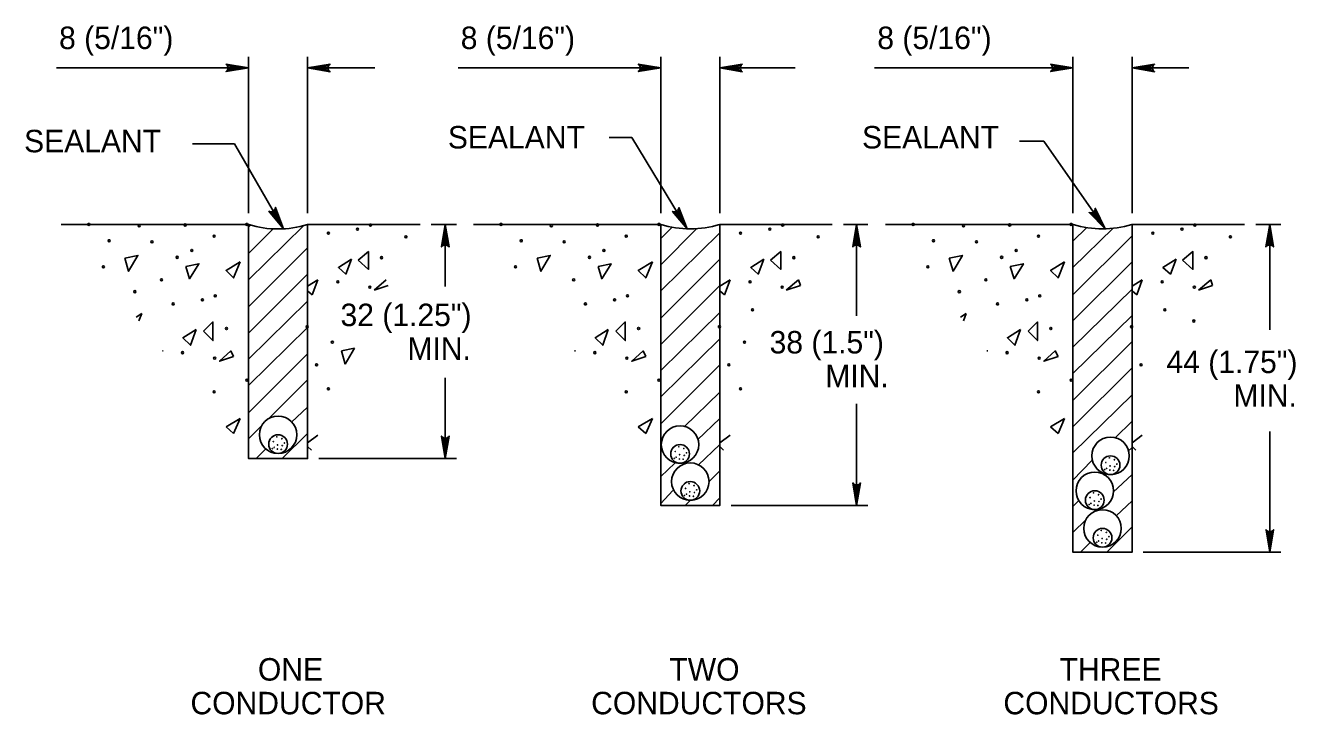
# Model space of a CAD drawing. Extents: x 2709 to 3899, y 22 to 1210.
# Drawn here: x 3729.8 to 3899.2, y 763.4 to 855.4 of the extents above; entities that cross this region are included whole.
import ezdxf

# ---------------------------------------------------------------- set-up
doc = ezdxf.new("R2010")
doc.units = 0
doc.layers.add('2', color=7, linetype='Continuous')
doc.layers.add('3', color=7, linetype='Continuous')

# ---------------------------------------------------------------- blocks, each defined once
blk = doc.blocks.new('RARROW')
at = {"layer": '3'}
blk.add_lwpolyline([(-2.2695, 0.285), (-2.184875, 0.12075), (0, 0), (-2.2695, 0.285), (-2.38575, 0.384625), (0, 0), (-2.183125, -0.108), (-2.262875, -0.2705), (0, 0), (-2.38575, -0.379125), (-2.262875, -0.2705)], dxfattribs=at)

msp = doc.modelspace()

# ---------------------------------------------------------------- linework, layer by layer
at = {"layer": '2'}
for p, q in [((3759.53, 830.32), (3759.53, 851.21)), ((3767.41, 830.32), (3767.41, 851.21)), ((3814.53, 830.32), (3814.53, 851.21)), ((3822.41, 830.32), (3822.41, 851.21)), ((3869.53, 830.32), (3869.53, 851.21)), ((3877.41, 830.32), (3877.41, 851.21)), ((3759.53, 849.71), (3733.89, 849.71)), ((3776.37, 849.71), (3767.41, 849.71)), ((3814.53, 849.71), (3787.48, 849.71)), ((3832.48, 849.71), (3822.41, 849.71)), ((3869.53, 849.71), (3843.06, 849.71)), ((3884.98, 849.71), (3877.41, 849.71)), ((3757.66, 839.57), (3752.03, 839.57)), ((3764.2, 828.24), (3757.66, 839.57)), ((3810.66, 840.44), (3807.66, 840.44)), ((3818.07, 828.25), (3810.66, 840.44)), ((3865.66, 839.94), (3862.41, 839.94)), ((3873.83, 828.25), (3865.66, 839.94)), ((3783.91, 828.82), (3787.28, 828.82)), ((3785.78, 828.82), (3785.78, 820.52)), ((3838.91, 828.82), (3842.16, 828.82)), ((3840.66, 828.82), (3840.66, 816.61)), ((3893.91, 828.82), (3897.28, 828.82)), ((3895.78, 828.82), (3895.78, 814.77)), ((3785.78, 808.33), (3785.78, 797.57)), ((3840.66, 804.88), (3840.66, 791.32)), ((3895.78, 801.2), (3895.78, 785.07)), ((3768.91, 797.57), (3787.28, 797.57)), ((3823.91, 791.32), (3842.16, 791.32)), ((3878.91, 785.07), (3897.28, 785.07))]:
    msp.add_line(p, q, dxfattribs=at)
for points in [[(3734.53, 828.82), (3759.53, 828.82), (3759.53, 797.57), (3767.41, 797.57), (3767.41, 828.82), (3782.41, 828.82)], [(3759.53, 828.44), (3759.81, 828.72)], [(3789.53, 828.82), (3814.53, 828.82), (3814.53, 791.32), (3822.41, 791.32), (3822.41, 828.82), (3837.41, 828.82)], [(3844.53, 828.82), (3869.53, 828.82), (3869.53, 785.07), (3877.41, 785.07), (3877.41, 828.82), (3892.41, 828.82)], [(3759.53, 821.44), (3766.87, 828.65)], [(3759.53, 824.94), (3762.83, 828.24)], [(3814.53, 826.94), (3816.05, 828.46)], [(3814.53, 823.44), (3819.36, 828.27)], [(3814.53, 819.94), (3822.41, 827.69)], [(3869.53, 826.57), (3871.37, 828.41)], [(3869.53, 823.07), (3874.91, 828.32)], [(3869.53, 819.44), (3877.41, 827.32)], [(3759.53, 817.82), (3767.41, 825.69)], [(3814.53, 816.32), (3822.41, 824.19)], [(3869.53, 815.94), (3877.41, 823.82)], [(3759.53, 814.32), (3767.41, 822.19)], [(3768.78, 821.44), (3767.41, 820.57)], [(3768.03, 819.44), (3768.78, 821.44)], [(3777.91, 821.44), (3776.28, 820.07)], [(3776.28, 820.07), (3778.16, 820.69)], [(3814.53, 812.82), (3822.41, 820.69)], [(3823.78, 821.44), (3822.41, 820.57)], [(3823.03, 819.44), (3823.78, 821.44)], [(3832.91, 821.44), (3831.28, 820.07)], [(3831.28, 820.07), (3833.16, 820.69)], [(3833.16, 820.69), (3832.91, 821.44)], [(3878.78, 821.44), (3877.41, 820.57)], [(3878.03, 819.44), (3878.78, 821.44)], [(3887.91, 821.44), (3886.28, 820.07)], [(3886.28, 820.07), (3888.16, 820.69)], [(3888.16, 820.69), (3887.91, 821.44)], [(3759.53, 810.82), (3767.41, 818.57)], [(3767.41, 819.94), (3768.03, 819.44)], [(3822.41, 819.94), (3823.03, 819.44)], [(3869.53, 812.44), (3877.41, 820.19)], [(3877.41, 819.94), (3878.03, 819.44)], [(3745.28, 816.94), (3744.53, 816.44)], [(3744.91, 815.94), (3745.28, 816.94)], [(3814.53, 809.32), (3822.41, 817.07)], [(3855.28, 816.94), (3854.53, 816.44)], [(3854.91, 815.94), (3855.28, 816.94)], [(3869.53, 808.94), (3877.41, 816.69)], [(3759.53, 807.32), (3767.41, 815.07)], [(3814.53, 805.82), (3822.41, 813.57)], [(3748.16, 811.94), (3748.03, 811.94)], [(3748.03, 811.94), (3748.16, 811.94)], [(3771.91, 811.94), (3773.66, 812.32)], [(3772.41, 810.19), (3771.91, 811.94)], [(3773.66, 812.32), (3772.41, 810.19)], [(3803.16, 811.94), (3803.03, 811.94)], [(3803.03, 811.94), (3803.16, 811.94)], [(3858.16, 811.94), (3858.03, 811.94)], [(3858.03, 811.94), (3858.16, 811.94)], [(3869.53, 805.32), (3877.41, 813.19)], [(3759.53, 803.69), (3767.41, 811.57)], [(3814.53, 802.19), (3822.41, 810.07)], [(3869.53, 801.82), (3877.41, 809.69)], [(3762.16, 802.82), (3767.41, 808.07)], [(3817.66, 801.82), (3822.41, 806.44)], [(3869.53, 798.32), (3877.41, 806.07)], [(3765.28, 802.44), (3767.41, 804.44)], [(3758.41, 802.94), (3756.53, 801.82)], [(3756.53, 801.82), (3757.53, 800.94)], [(3757.53, 800.94), (3758.41, 802.94)], [(3759.53, 800.19), (3761.28, 801.94)], [(3813.41, 802.94), (3811.53, 801.82)], [(3811.53, 801.82), (3812.53, 800.94)], [(3812.53, 800.94), (3813.41, 802.94)], [(3819.41, 800.07), (3822.41, 802.94)], [(3868.41, 802.94), (3866.53, 801.82)], [(3866.53, 801.82), (3867.53, 800.94)], [(3867.53, 800.94), (3868.41, 802.94)], [(3875.16, 800.32), (3877.41, 802.57)], [(3764.03, 797.57), (3767.41, 800.94)], [(3768.78, 800.69), (3767.41, 799.69)], [(3823.78, 800.69), (3822.41, 799.69)], [(3878.78, 800.69), (3877.41, 799.69)], [(3760.53, 797.57), (3761.78, 798.82)], [(3767.41, 799.19), (3767.91, 798.69)], [(3814.53, 798.69), (3814.66, 798.82)], [(3819.53, 796.69), (3822.41, 799.44)], [(3822.41, 799.19), (3822.91, 798.69)], [(3876.91, 798.57), (3877.41, 799.07)], [(3877.41, 799.19), (3877.91, 798.69)], [(3814.53, 795.19), (3816.41, 796.94)], [(3869.53, 794.69), (3872.03, 797.32)], [(3820.91, 794.44), (3822.41, 795.94)], [(3873.66, 795.32), (3873.78, 795.44)], [(3874.91, 793.07), (3877.41, 795.44)], [(3814.53, 791.57), (3816.16, 793.32)], [(3817.78, 791.32), (3818.41, 791.94)], [(3821.41, 791.32), (3822.41, 792.32)], [(3869.53, 791.19), (3870.28, 791.94)], [(3875.28, 789.94), (3877.41, 791.94)], [(3872.28, 790.44), (3872.53, 790.69)], [(3869.53, 787.69), (3871.28, 789.44)], [(3874.03, 785.07), (3877.41, 788.44)], [(3870.53, 785.07), (3871.78, 786.32)]]:
    msp.add_lwpolyline(points, dxfattribs=at)
for points in [[(3743.03, 824.32), (3744.78, 824.69), (3743.53, 822.57)], [(3758.41, 823.82), (3756.53, 822.69), (3757.53, 821.69)], [(3773.28, 824.19), (3771.53, 823.07), (3772.53, 822.19)], [(3774.16, 824.07), (3775.53, 825.19), (3775.53, 822.82)], [(3798.03, 824.32), (3799.78, 824.69), (3798.53, 822.57)], [(3813.41, 823.82), (3811.53, 822.69), (3812.53, 821.69)], [(3828.28, 824.19), (3826.53, 823.07), (3827.53, 822.19)], [(3829.16, 824.07), (3830.53, 825.19), (3830.53, 822.82)], [(3853.03, 824.32), (3854.78, 824.69), (3853.53, 822.57)], [(3868.41, 823.82), (3866.53, 822.69), (3867.53, 821.69)], [(3883.28, 824.19), (3881.53, 823.07), (3882.53, 822.19)], [(3884.16, 824.07), (3885.53, 825.19), (3885.53, 822.82)], [(3751.16, 823.19), (3752.91, 823.57), (3751.66, 821.57)], [(3806.16, 823.19), (3807.91, 823.57), (3806.66, 821.57)], [(3861.16, 823.19), (3862.91, 823.57), (3861.66, 821.57)], [(3753.53, 814.57), (3754.78, 815.82), (3754.78, 813.32)], [(3808.53, 814.57), (3809.78, 815.82), (3809.78, 813.32)], [(3863.53, 814.57), (3864.78, 815.82), (3864.78, 813.32)], [(3752.53, 814.82), (3750.78, 813.69), (3751.78, 812.69)], [(3807.53, 814.82), (3805.78, 813.69), (3806.78, 812.69)], [(3862.53, 814.82), (3860.78, 813.69), (3861.78, 812.69)], [(3757.53, 811.19), (3757.16, 811.94), (3755.66, 810.57)], [(3812.53, 811.19), (3812.16, 811.94), (3810.66, 810.57)], [(3867.53, 811.19), (3867.16, 811.94), (3865.66, 810.57)]]:
    msp.add_lwpolyline(points, close=True, dxfattribs=at)
for centre, radius in [((3738.21, 828.83), 0.138), ((3744.93, 828.63), 0.138), ((3751.08, 828.75), 0.138), ((3759.29, 828.83), 0.138), ((3775.79, 828.74), 0.138), ((3793.21, 828.83), 0.138), ((3799.93, 828.63), 0.138), ((3806.08, 828.75), 0.138), ((3814.29, 828.83), 0.138), ((3830.79, 828.74), 0.138), ((3848.21, 828.83), 0.138), ((3854.93, 828.63), 0.138), ((3861.08, 828.75), 0.138), ((3869.29, 828.83), 0.138), ((3885.79, 828.74), 0.138), ((3754.93, 827.26), 0.138), ((3770.18, 827.67), 0.138), ((3774.07, 828.2), 0.138), ((3780.53, 827.17), 0.138), ((3809.93, 827.26), 0.138), ((3825.18, 827.67), 0.138), ((3829.07, 828.2), 0.138), ((3835.53, 827.17), 0.138), ((3864.93, 827.26), 0.138), ((3880.18, 827.67), 0.138), ((3884.07, 828.2), 0.138), ((3890.53, 827.17), 0.138), ((3740.92, 826.65), 0.138), ((3746.65, 826.5), 0.138), ((3751.95, 825.35), 0.138), ((3795.92, 826.65), 0.138), ((3801.65, 826.5), 0.138), ((3806.95, 825.35), 0.138), ((3850.92, 826.65), 0.138), ((3856.65, 826.5), 0.138), ((3861.95, 825.35), 0.138), ((3750.01, 824.43), 0.138), ((3777.28, 824.39), 0.138), ((3805.01, 824.43), 0.138), ((3832.28, 824.39), 0.138), ((3860.01, 824.43), 0.138), ((3887.28, 824.39), 0.138), ((3740.16, 823.17), 0.138), ((3795.16, 823.17), 0.138), ((3850.16, 823.17), 0.138), ((3747.91, 821.42), 0.138), ((3771.44, 821.16), 0.138), ((3775.72, 820.44), 0.138), ((3802.91, 821.42), 0.138), ((3826.44, 821.16), 0.138), ((3830.72, 820.44), 0.138), ((3857.91, 821.42), 0.138), ((3881.44, 821.16), 0.138), ((3885.72, 820.44), 0.138), ((3744.36, 819.85), 0.138), ((3753.37, 818.75), 0.138), ((3755.09, 819.28), 0.138), ((3808.37, 818.75), 0.138), ((3810.09, 819.28), 0.138), ((3854.36, 819.85), 0.138), ((3863.37, 818.75), 0.138), ((3865.09, 819.28), 0.138), ((3749.47, 818.21), 0.138), ((3804.47, 818.21), 0.138), ((3826.78, 817.42), 0.138), ((3859.47, 818.21), 0.138), ((3881.78, 817.42), 0.138), ((3767.35, 815.17), 0.138), ((3822.35, 815.17), 0.138), ((3877.35, 815.17), 0.138), ((3885.64, 815.93), 0.138), ((3756.58, 814.93), 0.138), ((3811.58, 814.93), 0.138), ((3866.58, 814.93), 0.138), ((3750.73, 811.71), 0.138), ((3770.71, 813.11), 0.138), ((3805.73, 811.71), 0.138), ((3825.71, 813.11), 0.138), ((3860.73, 811.71), 0.138), ((3755.01, 810.98), 0.138), ((3768.61, 810.09), 0.138), ((3810.01, 810.98), 0.138), ((3823.61, 810.09), 0.138), ((3865.01, 810.98), 0.138), ((3878.61, 810.09), 0.138), ((3759.29, 808.04), 0.138), ((3770.18, 806.89), 0.138), ((3814.29, 808.04), 0.138), ((3825.18, 806.89), 0.138), ((3869.29, 808.04), 0.138), ((3754.93, 806.48), 0.138), ((3809.93, 806.48), 0.138), ((3864.93, 806.48), 0.138), ((3763.47, 800.75), 2.5), ((3817.1, 799.44), 2.5), ((3763.47, 799.5), 1.25), ((3762.72, 800.48), 0.0249), ((3763.31, 800.47), 0.0249), ((3763.98, 800.22), 0.0249), ((3874.54, 797.94), 2.5), ((3762.7, 798.91), 0.0249), ((3762.84, 799.84), 0.0249), ((3762.95, 799.07), 0.0249), ((3763.38, 798.84), 0.0249), ((3763.41, 799.4), 0.0249), ((3763.89, 798.8), 0.0249), ((3764.03, 799.31), 0.0249), ((3764.32, 799.65), 0.0249), ((3817.1, 798.19), 1.25), ((3816.35, 799.17), 0.0249), ((3816.47, 798.52), 0.0249), ((3816.94, 799.16), 0.0249), ((3817.61, 798.9), 0.0249), ((3817.95, 798.34), 0.0249), ((3818.47, 794.5), 2.5), ((3816.33, 797.6), 0.0249), ((3816.58, 797.75), 0.0249), ((3817.01, 797.52), 0.0249), ((3817.04, 798.09), 0.0249), ((3817.51, 797.49), 0.0249), ((3817.66, 798), 0.0249), ((3874.54, 796.69), 1.25), ((3873.79, 797.67), 0.0249), ((3873.91, 797.03), 0.0249), ((3874.38, 797.67), 0.0249), ((3874.48, 796.59), 0.0249), ((3875.05, 797.41), 0.0249), ((3875.1, 796.5), 0.0249), ((3875.39, 796.84), 0.0249), ((3872.44, 793.27), 2.5), ((3873.77, 796.1), 0.0249), ((3874.02, 796.26), 0.0249), ((3874.45, 796.03), 0.0249), ((3874.96, 795.99), 0.0249), ((3818.47, 793.25), 1.25), ((3817.72, 794.23), 0.0249), ((3817.84, 793.59), 0.0249), ((3818.31, 794.22), 0.0249), ((3818.41, 793.15), 0.0249), ((3818.98, 793.97), 0.0249), ((3819.32, 793.4), 0.0249), ((3872.44, 792.02), 1.25), ((3817.7, 792.66), 0.0249), ((3817.95, 792.82), 0.0249), ((3818.38, 792.59), 0.0249), ((3818.89, 792.55), 0.0249), ((3819.03, 793.06), 0.0249), ((3871.67, 791.44), 0.0249), ((3871.69, 793), 0.0249), ((3871.81, 792.36), 0.0249), ((3871.92, 791.59), 0.0249), ((3872.28, 793), 0.0249), ((3872.38, 791.92), 0.0249), ((3872.95, 792.74), 0.0249), ((3873, 791.84), 0.0249), ((3873.28, 792.17), 0.0249), ((3873.47, 788.25), 2.5), ((3872.35, 791.36), 0.0249), ((3872.85, 791.32), 0.0249), ((3873.47, 787), 1.25), ((3872.7, 786.41), 0.0249), ((3872.72, 787.98), 0.0249), ((3872.84, 787.34), 0.0249), ((3872.95, 786.57), 0.0249), ((3873.31, 787.97), 0.0249), ((3873.38, 786.34), 0.0249), ((3873.41, 786.9), 0.0249), ((3873.98, 787.72), 0.0249), ((3874.03, 786.81), 0.0249), ((3874.32, 787.15), 0.0249), ((3873.89, 786.3), 0.0249)]:
    msp.add_circle(centre, radius, dxfattribs=at)
for centre in [(3763.47, 841.82), (3818.47, 841.84), (3873.46, 841.84)]:
    msp.add_arc(centre, 13.6, 253.303, 286.697, dxfattribs=at)

# ---------------------------------------------------------------- block references
at = {"layer": '2', "xscale": 1.2574347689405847, "yscale": 1.3092961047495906}
for p in [(3759.53, 849.71), (3814.53, 849.71), (3869.53, 849.71)]:
    msp.add_blockref('RARROW', p, dxfattribs=at)
at = {"layer": '2'}
for p, xscale, yscale, rotation in [((3767.41, 849.71), 1.2574347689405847, 1.3092961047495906, 180), ((3822.41, 849.71), 1.2574347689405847, 1.3092961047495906, 180), ((3877.41, 849.71), 1.2574347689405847, 1.3092961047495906, 180), ((3764.2, 828.24), 1.2574347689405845, 1.3092961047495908, -59.693392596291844), ((3818.07, 828.25), 1.2574347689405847, 1.3092961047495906, -58.91242877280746), ((3873.83, 828.25), 1.2574347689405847, 1.3092961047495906, -54.5014105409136), ((3785.78, 828.82), 1.2574347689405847, 1.3092961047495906, 89.99999999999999), ((3840.66, 828.82), 1.2574347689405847, 1.3092961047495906, 89.99999999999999), ((3895.78, 828.82), 1.2574347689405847, 1.3092961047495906, 89.99999999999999), ((3785.78, 797.57), 1.2574347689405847, 1.3092961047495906, -90.00000000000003), ((3840.66, 791.32), 1.2574347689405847, 1.3092961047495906, -90.00000000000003), ((3895.78, 785.07), 1.2574347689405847, 1.3092961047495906, -90.00000000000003)]:
    msp.add_blockref('RARROW', p, dxfattribs=dict(at, xscale=xscale, yscale=yscale, rotation=rotation))

# ---------------------------------------------------------------- texts
for s, p in [('8 (5/16") ', (3734.25, 852.23)), ('8 (5/16") ', (3787.84, 852.23)), ('8 (5/16") ', (3843.42, 852.23)), ('SEALANT', (3729.58, 838.45)), ('SEALANT', (3786.12, 838.96)), ('SEALANT', (3841.38, 838.96)), ('32 (1.25")', (3771.8, 815.25)), ('MIN.', (3780.73, 810.75)), ('38 (1.5")', (3829.05, 811.6)), ('44 (1.75")', (3882, 808.98)), ('MIN.', (3836.48, 807.1)), ('MIN.', (3890.93, 804.48)), ('ONE', (3760.78, 767.94)), ('TWO', (3815.68, 767.94)), ('THREE', (3867.74, 767.94)), ('CONDUCTOR', (3751.78, 763.44)), ('CONDUCTORS', (3805.24, 763.44)), ('CONDUCTORS', (3860.24, 763.44))]:
    msp.add_text(s, height=3, dxfattribs=at).set_placement(p)

doc.saveas('drawing.dxf')
